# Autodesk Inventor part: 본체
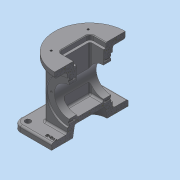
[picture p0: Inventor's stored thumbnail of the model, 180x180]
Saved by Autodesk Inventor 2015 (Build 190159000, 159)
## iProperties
Created: 2021-05
Part Number: 본체
Material: 일반
Document SubType Name: Modeling
Designer: 101258642
Density: 1 g/cm^3
Appearance: 기본값
Author: 101258642
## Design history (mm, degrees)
sketch "스케치6"
  geometry: L1 (37, -37)-(-37, -37); L2 (-37, -37)-(-37, 37); L3 (-37, 37)-(37, 37); L4 (37, 37)-(37, -37); L5 (37, -37)-(-37, 37); L6 (-37, -37)-(37, 37); 1 further point
  constraints: 12 end point, 2 midpoint, 2 parallel, 1 horizontal, 1 perpendicular
  dimensions: "d4" = 74 distance of L2.end L3.end; "d5" = 74 distance of L1.end L2.end
extrude "돌출2" new body sketch "스케치6" stored distance "d6" = 108; taper "d7" = 0 deg
sketch "스케치7"
  geometry: C1 r 57.5 at (0, 0); 1 further point
  constraints: 1 centre point, 1 coincident
  dimensions: "d8" = 57.5 radius of C1
extrude "돌출3" join sketch "스케치7" distance "d9" = 10; taper "d10" = 0 deg
sketch "스케치8"
  geometry: L1 (-62.5, 62.5)-(62.5, 62.5); L2 (62.5, 62.5)-(62.5, -62.5); L3 (62.5, -62.5)-(-62.5, -62.5); L4 (-62.5, -62.5)-(-62.5, 62.5); L5 (-62.5, 62.5)-(62.5, -62.5); L6 (62.5, 62.5)-(-62.5, -62.5); 1 further point
  constraints: 12 end point, 2 midpoint, 2 parallel, 1 horizontal, 1 perpendicular
  dimensions: "d11" = 125 distance of L2.end L3.end; "d12" = 125 distance of L1.end L2.end
extrude "돌출4" join sketch "스케치8" distance "d13" = 10; taper "d14" = 0 deg
sketch "스케치9"
  geometry: L1 (-37, 44)-(-57.5, 44) reference; L2 (-57.5, 44)-(-57.5, 54) reference; L3 (-57.5, 54)-(57.5, 54) reference; L4 (57.5, 54)-(57.5, 44) reference; L5 (57.5, 44)-(37, 44) reference; L6 (37, 44)-(37, -44) reference; L7 (37, -44)-(62.5, -44) reference; L8 (62.5, -44)-(62.5, -54) reference; L9 (62.5, -54)-(-62.5, -54) reference; L10 (-62.5, -54)-(-62.5, -44) reference; L11 (-62.5, -44)-(-37, -44) reference; L12 (-37, -44)-(-37, 44) reference; L13 (-37, 0)-(-34, 0); L14 (-34, 0)-(-34, 35); L15 (-34, 35)-(-37, 35); L16 (-37, 35)-(-37, 0); L17 (37, 44)-(37, -44) reference; L18 (37, 35)-(34, 35); L19 (34, 35)-(34, 0); L20 (34, 0)-(37, 0); L21 (37, 0)-(37, 35); L22 (-34, 0)-(34, 0); L23 (34, 0)-(34, 24); L24 (34, 24)-(-34, 24); L25 (-34, 24)-(-34, 0); 1 further point
  constraints: 24 end point, 6 parallel, 3 horizontal, 3 perpendicular, 3 point on line, 1 midpoint
  dimensions: "d15" = 54 distance between parallel lines of L9 L13; "d16" = 3 distance of L14.end L15.end; "d17" = 3 distance of L18.start L18.end; "d18" = 48 diameter of L24 L22; "d19" = 70 diameter of L15 L22; "d20" = 70 diameter of L18 L20
revolve "회전1" sketch "스케치9" stored, may be unused: angle "d21" = 90 deg
sketch "스케치11"
  geometry: L1 (-26, 26)-(26, 26); L2 (26, 26)-(26, -26); L3 (26, -26)-(-26, -26); L4 (-26, -26)-(-26, 26); L5 (-26, 26)-(26, -26); L6 (26, 26)-(-26, -26); C1 r 57.5 at (0, 0) reference
  constraints: 12 end point, 2 midpoint, 2 parallel, 1 horizontal, 1 perpendicular
  dimensions: "d26" = 52 distance of L2.end L3.end; "d27" = 52 distance of L1.end L2.end
extrude "돌출6" cut sketch "스케치11" distance "d28" = 8; taper "d29" = 0 deg
sketch "스케치12" dims "d30" = 29
  geometry: C1 r 35 at (0, 0) reference; 2 further points
  constraints: 1 coincident, 1 vertical alignment, 2 other
hole "구멍1" sketch "스케치12" at (0, 29) diameter "d31" = 3.242; stored, may be unused: countersink angle "d35" = 90 deg, drill point angle "d37" = 118 deg; dims "d32" = 8, "d33" = 4, "d34" = 2, "d36" = 10
sketch "스케치13"
  geometry: L1 (-30, 33)-(30, 33); L2 (30, 33)-(30, -33); L3 (30, -33)-(-30, -33); L4 (-30, -33)-(-30, 33); L5 (-30, 33)-(30, -33); L6 (30, 33)-(-30, -33); C1 r 57.5 at (0, 0) reference; 4 further points
  constraints: 12 end point, 4 coincident, 2 midpoint, 2 parallel, 1 horizontal, 1 perpendicular
  dimensions: "d41" = 60 distance of L2.end L3.end; "d42" = 66 distance of L1.end L2.end
hole "구멍2" sketch "스케치13" at (-30, -33), (-30, 33), (30, 33), (30, -33) diameter "d43" = 3.242; stored, may be unused: countersink angle "d47" = 90 deg, drill point angle "d49" = 118 deg; dims "d44" = 8, "d45" = 4, "d46" = 2, "d48" = 10
fillet "모깎기1" dims "d50" = 12
hole "구멍3" diameter "d53" = 9; stored, may be unused: countersink angle "d57" = 90 deg, drill point angle "d59" = 0 deg; dims "d51" = 10, "d52" = 10, "d54" = 8, "d55" = 4, "d56" = 2, "d58" = 10
sketch "스케치15"
  geometry: L1 (26, 46)-(26, 54) reference; L2 (26, 54)-(57.5, 54) reference; L3 (57.5, 54)-(57.5, 44) reference; L4 (57.5, 44)-(37, 44) reference; L5 (37, 44)-(37, 35) reference; L6 (37, 35)-(34, 35) reference; L7 (34, 35)-(34, 30.621) reference; L8 (34, 30.621)-(24, 30.621) reference; L9 (24, 30.621)-(23.026, 29) reference; L10 (23.026, 29)-(24, 27.379) reference; L11 (24, 27.379)-(34, 27.379) reference; L12 (34, 27.379)-(34, 24) reference; L13 (34, 24)-(-34, 24) reference; L14 (-26, 46)-(26, 46) reference; L15 (-34, -24)-(34, -24) reference; L16 (34, -24)-(34, -27.379) reference; L17 (34, -27.379)-(24, -27.379) reference; L18 (24, -27.379)-(23.026, -29) reference; L19 (23.026, -29)-(24, -30.621) reference; L20 (24, -30.621)-(34, -30.621) reference; L21 (34, -30.621)-(34, -35) reference; L22 (34, -35)-(37, -35) reference; L23 (37, -35)-(37, -44) reference; L24 (37, -44)-(62.5, -44) reference; L25 (62.5, -44)-(62.5, -54) reference; L26 (62.5, -54)-(-62.5, -54) reference; L27 (-62.5, -54)-(-62.5, -44) reference; L28 (-62.5, -44)-(-37, -44) reference; L29 (-37, -44)-(-37, -35) reference; L30 (-37, -35)-(-34, -35) reference; L31 (-34, -35)-(-34, -30.621) reference; L32 (-34, -30.621)-(-24, -30.621) reference; L33 (-24, -30.621)-(-23.026, -29) reference; L34 (-23.026, -29)-(-24, -27.379) reference; L35 (-24, -27.379)-(-34, -27.379) reference; L36 (-34, -27.379)-(-34, -24) reference; L37 (-37, 44)-(-57.5, 44) reference; L38 (-57.5, 44)-(-57.5, 54) reference; L39 (-57.5, 54)-(-26, 54) reference; L40 (-26, 54)-(-26, 46) reference; L41 (-34, 24)-(-34, 27.379) reference; L42 (-34, 27.379)-(-24, 27.379) reference; L43 (-24, 27.379)-(-23.026, 29) reference; L44 (-23.026, 29)-(-24, 30.621) reference; L45 (-24, 30.621)-(-34, 30.621) reference; L46 (-34, 30.621)-(-34, 35) reference; L47 (-34, 35)-(-37, 35) reference; L48 (-37, 35)-(-37, 44) reference; L49 (-28, -54)-(-24.826, -36); L50 (-24.826, -36)-(0, -36); L51 (0, -36)-(0, -54); L52 (50.5, -54)-(-50.5, -54) reference; L53 (-28, -54)-(0, -54); 2 further points
  constraints: 8 end point, 2 midpoint, 1 collinear, 1 horizontal, 1 point on line, 1 vertical alignment
  dimensions: "d66" = 80 deg angle of L53 L49; "d67" = 56 diameter of L49.start L51; "d68" = 18 distance between parallel lines of L53 L50
revolve "회전2" sketch "스케치15" stored, may be unused: angle "d69" = 90 deg
sketch "스케치21"
  geometry: L1 (-22, 22)-(22, 22); L2 (22, 22)-(22, -22); L3 (22, -22)-(-22, -22); L4 (-22, -22)-(-22, 22); L5 (-22, 22)-(22, -22); L6 (22, 22)-(-22, -22); 1 further point
  constraints: 12 end point, 2 midpoint, 2 parallel, 1 horizontal, 1 perpendicular
  dimensions: "d71" = 44 distance of L2.end L3.end; "d72" = 44 distance of L1.end L2.end
extrude "돌출7" cut sketch "스케치21" distance "d73" = 74; taper "d74" = 0 deg
sketch "스케치23"
  geometry: L1 (-13.5, -98)-(87.5, -98) reference; 3 further points
  constraints: 2 vertical alignment
  dimensions: "d75" = 43 distance of point (37, -61) point (37, -18); "d76" = 37 distance from line of L1 point (37, -61)
hole "구멍4" sketch "스케치23" at (37, -18), (37, -61) diameter "d77" = 4.134; stored, may be unused: countersink angle "d81" = 90 deg, drill point angle "d83" = 118 deg; dims "d78" = 10, "d79" = 4, "d80" = 2, "d82" = 30
fillet "모깎기2" dims "d84" = 3
fillet "모깎기3" dims "d85" = 3
fillet "모깎기4" dims "d86" = 3
fillet "모깎기5" dims "d87" = 3
fillet "모깎기7" dims "d92" = 6
chamfer "모따기2" distance "d93" = 1; stored, may be unused: second distance "d94" = 2, angle "d95" = 45 deg
node "작업 평면1"
sketch "스케치24"
  geometry: L1 (51.783, -16.923)-(51.783, 16.26); L2 (51.783, 16.26)-(58.217, 16.26); L3 (58.217, 16.26)-(58.217, -16.923); L4 (58.217, -16.923)-(51.783, -16.923); 2 further points
  constraints: 1 midpoint, 2 other
  dimensions: "d98" = 55 horizontal distance of point (0, 0) point (55, 16.26)
feature "엠보싱1" sketch "스케치24" dims "d4" = 74, "d5" = 74, "d99" = 0.5, "d100" = 0
node "솔리드2"
pattern_circular "원형 패턴1" dims angle "d39" = 360 deg
mirror "대칭1"
pattern_linear "직사각형 패턴1"
node "절단 모서리 투영1"
node "절단 모서리 투영2"
